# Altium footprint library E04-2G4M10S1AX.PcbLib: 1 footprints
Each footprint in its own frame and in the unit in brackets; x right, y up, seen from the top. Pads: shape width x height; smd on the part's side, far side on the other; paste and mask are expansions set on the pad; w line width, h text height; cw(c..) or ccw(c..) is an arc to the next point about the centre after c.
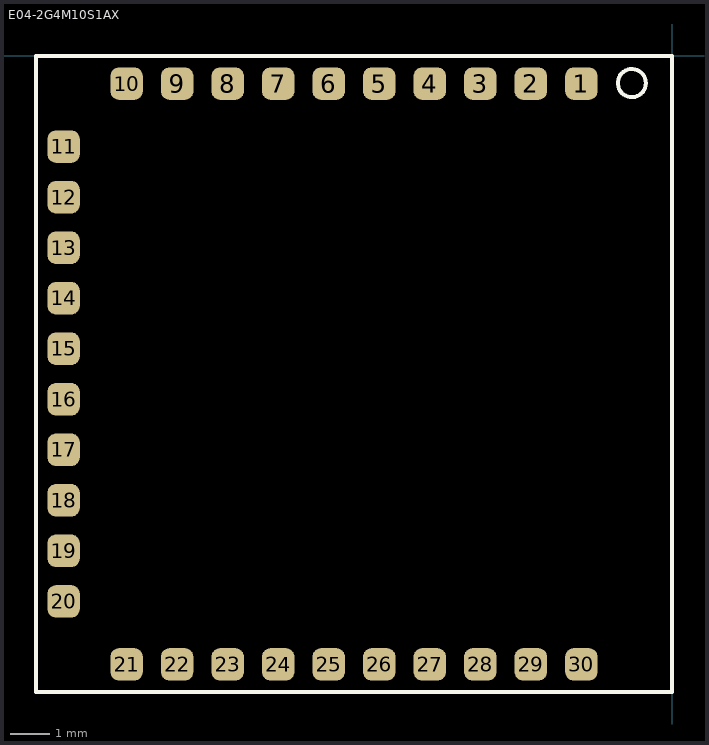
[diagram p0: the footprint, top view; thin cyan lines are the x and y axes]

## E04-2G4M10S1AX [mm]
pads (30):
  rrect50% 0.81x0.81 smd paste-0.05 mask-0.05: 1(-2.285,-0.7) 2(-3.555,-0.7) 3(-4.825,-0.7) 4(-6.095,-0.7) 5(-7.365,-0.7) 6(-8.635,-0.7) 7(-9.905,-0.7) 8(-11.175,-0.7) 9(-12.445,-0.7) 10(-13.715,-0.7) 11(-15.3,-2.285) 12(-15.3,-3.555) 13(-15.3,-4.825) 14(-15.3,-6.095) 15(-15.3,-7.365) 16(-15.3,-8.635) 17(-15.3,-9.905) 18(-15.3,-11.175) 19(-15.3,-12.445) 20(-15.3,-13.715) 21(-13.715,-15.3) 22(-12.445,-15.3) 23(-11.175,-15.3) 24(-9.905,-15.3) 25(-8.635,-15.3) 26(-7.365,-15.3) 27(-6.095,-15.3) 28(-4.825,-15.3) 29(-3.555,-15.3) 30(-2.285,-15.3)
Top Overlay:
  circle w0.1: c-1.014,-0.686 r0.354
  lines w0.1: -16,-16 -16,0 0,0 0,-16 -16,-16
